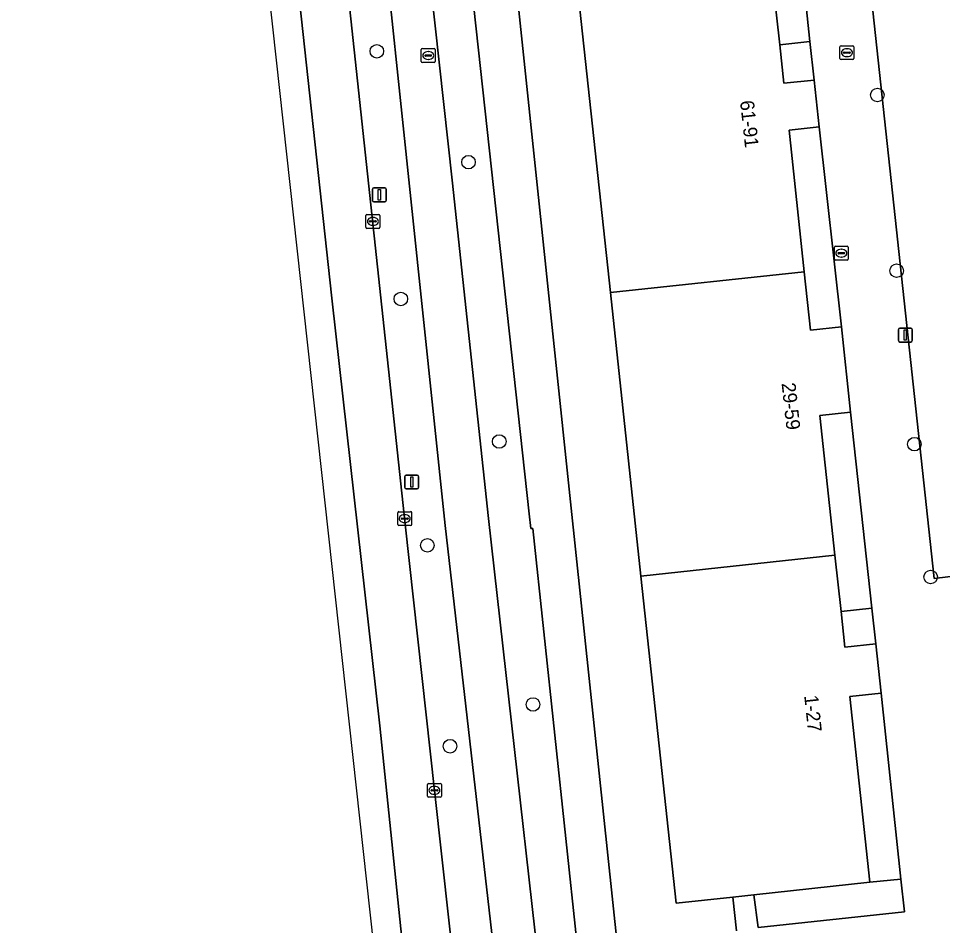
# Model space of a CAD drawing. Extents: x 161248 to 161848, y 384871 to 385383.
# Drawn here: x 161255.9 to 161322.5, y 385046.9 to 385112.2 of the extents above; entities that cross this region are included whole.
import ezdxf

# ---------------------------------------------------------------- set-up
doc = ezdxf.new("R2010")
doc.units = 0
for name, color, linetype in [('IMGEO_Berm_groen', 7, 'Continuous'), ('IMGEO_Boom', 7, 'Continuous'), ('IMGEO_Brandkraan', 7, 'Continuous'), ('IMGEO_Fietspad_gesloten', 7, 'Continuous'), ('IMGEO_Groenvoorziening', 7, 'Continuous'), ('IMGEO_Kolk', 7, 'Continuous'), ('IMGEO_Lichtmast', 7, 'Continuous'), ('IMGEO_OVBaan_gesloten', 7, 'Continuous'), ('IMGEO_Pand', 7, 'Continuous'), ('IMGEO_Pand_nummerreeks', 7, 'Continuous'), ('IMGEO_Parkeervlak_open', 7, 'Continuous'), ('IMGEO_Rioolput', 7, 'Continuous'), ('IMGEO_Voetpad_open', 7, 'Continuous')]:
    doc.layers.add(name, color=color, linetype=linetype)

msp = doc.modelspace()

# ---------------------------------------------------------------- linework, layer by layer
at = {"layer": 'IMGEO_Berm_groen'}
for points in [[(161256.654, 385321.916), (161257.172, 385317.445), (161257.661, 385313.23), (161259.702, 385295.859), (161261.967, 385276.513), (161264.604, 385254.141), (161265.807, 385244.078), (161266.037, 385241.979), (161266.267, 385239.966), (161268.56, 385218.577), (161268.655, 385216.841), (161268.939, 385214.138), (161270.794, 385196.453), (161276.441, 385144.086), (161283.784, 385075.774), (161285.879, 385056.617), (161288.02, 385037.301), (161290.772, 385012.005), (161294.901, 384976.402), (161297.066, 384956.529), (161299.154, 384937.372), (161301.048, 384920.049), (161301.427, 384916.232), (161301.431, 384916.18)], [(161275.66, 385206.665), (161282.325, 385144.732), (161283.468, 385134.103), (161287.158, 385100.538), (161289.778, 385076.19), (161294.971, 385029.929), (161297.713, 385030.826), (161292.978, 385075.471), (161292.829, 385075.469), (161292.7, 385076.509), (161285.204, 385145.048)], [(161304.405, 384916.554), (161304.284, 384917.771), (161304.157, 384919.005), (161298.845, 384967.161), (161292.634, 385023.456), (161286.649, 385075.675), (161279.435, 385144.415)]]:
    msp.add_lwpolyline(points, dxfattribs=at)
at = {"layer": 'IMGEO_Boom'}
for centre in [(161281.733, 385109.811), (161317.773, 385106.667), (161288.335, 385101.832), (161319.163, 385094.019), (161283.464, 385091.987), (161290.547, 385081.724), (161320.439, 385081.536), (161285.374, 385074.251), (161321.612, 385071.974), (161292.98, 385062.798), (161287.005, 385059.792)]:
    msp.add_circle(centre, 0.489, dxfattribs=at)
at = {"layer": 'IMGEO_Brandkraan'}
for p, q in [((161315.083, 385109.287), (161315.083, 385110.139)), ((161315.158, 385110.213), (161316.01, 385110.213)), ((161315.342, 385109.707), (161315.342, 385109.719)), ((161315.385, 385109.756), (161315.783, 385109.756)), ((161315.571, 385109.993), (161315.596, 385109.993)), ((161315.826, 385109.719), (161315.826, 385109.707)), ((161316.084, 385110.139), (161316.084, 385109.287)), ((161316.01, 385109.213), (161315.158, 385109.213)), ((161315.78, 385109.67), (161315.382, 385109.67)), ((161315.594, 385109.433), (161315.569, 385109.433))]:
    msp.add_line(p, q, dxfattribs=at)
for points in [[(161315.083, 385109.287), (161315.083, 385110.139)], [(161315.158, 385110.213), (161316.01, 385110.213)], [(161316.084, 385110.139), (161316.084, 385109.287)], [(161316.01, 385109.213), (161315.158, 385109.213)]]:
    msp.add_lwpolyline(points, dxfattribs=at)
for centre, radius, start, end in [((161315.16, 385110.137), 0.0765, 91.55205, 178.44795), ((161315.16, 385110.137), 0.0765, 91.55205, 178.44795), ((161315.382, 385109.716), 0.0403, 85.87752, 175.75265), ((161315.379, 385109.706), 0.0366, 178.93798, 274.71019), ((161315.783, 385109.713), 0.043, 264.86636, 352.45326), ((161315.787, 385109.718), 0.0386, 1.73085, 96.63898), ((161316.008, 385110.137), 0.0765, 1.55205, 88.44795), ((161316.008, 385110.137), 0.0765, 1.55205, 88.44795), ((161315.16, 385109.289), 0.0765, 181.55205, 268.44795), ((161315.16, 385109.289), 0.0765, 181.55205, 268.44795), ((161316.008, 385109.289), 0.0765, 271.55205, 358.44795), ((161316.008, 385109.289), 0.0765, 271.55205, 358.44795)]:
    msp.add_arc(centre, radius, start, end, dxfattribs=at)
for centre, major_axis, ratio, start_param, end_param in [((161315.57, 385109.713), (-0.387, 0.002), 0.722429, 4.712389, 7.853982), ((161315.595, 385109.713), (-0.39, 0.002), 0.717154, 1.570796, 4.712389)]:
    msp.add_ellipse(centre, major_axis=major_axis, ratio=ratio, start_param=start_param, end_param=end_param, dxfattribs=at)
at = {"layer": 'IMGEO_Fietspad_gesloten'}
for points in [[(161255.931, 385327.627), (161256.339, 385324.574), (161264.625, 385325.002), (161264.745, 385322.761), (161265.427, 385312.935), (161265.987, 385305.638), (161266.061, 385304.636), (161266.954, 385291.9), (161268.918, 385265.585), (161269.728, 385255.799), (161270.412, 385243.981), (161271.091, 385227.08), (161272.519, 385207.639), (161273.278, 385201.438), (161279.435, 385144.415), (161286.649, 385075.675), (161292.634, 385023.456), (161298.845, 384967.161), (161304.157, 384919.005), (161304.284, 384917.771), (161304.405, 384916.554)], [(161295.082, 385029.016), (161294.971, 385029.929), (161289.778, 385076.19), (161287.158, 385100.538), (161283.468, 385134.103), (161282.325, 385144.732), (161275.66, 385206.665)]]:
    msp.add_lwpolyline(points, dxfattribs=at)
at = {"layer": 'IMGEO_Groenvoorziening'}
for points in [[(161288.519, 385145.411), (161295.732, 385076.938), (161299.044, 385045.595)], [(161307.622, 385046.516), (161307.357, 385048.936), (161303.279, 385048.497), (161300.745, 385072.04), (161298.549, 385092.443), (161296.352, 385112.845)]]:
    msp.add_lwpolyline(points, dxfattribs=at)
at = {"layer": 'IMGEO_Kolk'}
for p, q in [((161280.95, 385097.143), (161280.95, 385097.995)), ((161281.025, 385098.069), (161281.877, 385098.069)), ((161281.438, 385097.849), (161281.463, 385097.849)), ((161281.951, 385097.995), (161281.951, 385097.143)), ((161281.877, 385097.069), (161281.025, 385097.069)), ((161281.209, 385097.563), (161281.209, 385097.575)), ((161281.647, 385097.526), (161281.249, 385097.526)), ((161281.252, 385097.612), (161281.65, 385097.612)), ((161281.461, 385097.289), (161281.436, 385097.289)), ((161281.693, 385097.575), (161281.693, 385097.563)), ((161283.241, 385075.749), (161283.241, 385076.601)), ((161283.316, 385076.675), (161284.168, 385076.675)), ((161283.729, 385076.455), (161283.754, 385076.455)), ((161284.242, 385076.601), (161284.242, 385075.749)), ((161283.5, 385076.169), (161283.5, 385076.181)), ((161283.938, 385076.132), (161283.54, 385076.132)), ((161283.543, 385076.218), (161283.941, 385076.218)), ((161283.752, 385075.895), (161283.727, 385075.895)), ((161283.984, 385076.181), (161283.984, 385076.169)), ((161284.168, 385075.675), (161283.316, 385075.675)), ((161285.453, 385057.117), (161286.305, 385057.117)), ((161285.378, 385056.191), (161285.378, 385057.043)), ((161285.637, 385056.611), (161285.637, 385056.623)), ((161286.075, 385056.574), (161285.677, 385056.574)), ((161285.68, 385056.66), (161286.078, 385056.66)), ((161285.866, 385056.897), (161285.891, 385056.897)), ((161286.121, 385056.623), (161286.121, 385056.611)), ((161286.379, 385057.043), (161286.379, 385056.191)), ((161286.305, 385056.117), (161285.453, 385056.117)), ((161285.889, 385056.337), (161285.864, 385056.337))]:
    msp.add_line(p, q, dxfattribs=at)
for points in [[(161280.95, 385097.143), (161280.95, 385097.995)], [(161281.025, 385098.069), (161281.877, 385098.069)], [(161281.951, 385097.995), (161281.951, 385097.143)], [(161281.877, 385097.069), (161281.025, 385097.069)], [(161283.241, 385075.749), (161283.241, 385076.601)], [(161283.316, 385076.675), (161284.168, 385076.675)], [(161284.242, 385076.601), (161284.242, 385075.749)], [(161284.168, 385075.675), (161283.316, 385075.675)], [(161285.453, 385057.117), (161286.305, 385057.117)], [(161285.378, 385056.191), (161285.378, 385057.043)], [(161286.379, 385057.043), (161286.379, 385056.191)], [(161286.305, 385056.117), (161285.453, 385056.117)]]:
    msp.add_lwpolyline(points, dxfattribs=at)
for centre, radius, start, end in [((161281.027, 385097.993), 0.0765, 91.55205, 178.44795), ((161281.027, 385097.993), 0.0765, 91.55205, 178.44795), ((161281.875, 385097.993), 0.0765, 1.55205, 88.44795), ((161281.875, 385097.993), 0.0765, 1.55205, 88.44795), ((161281.027, 385097.145), 0.0765, 181.55205, 268.44795), ((161281.027, 385097.145), 0.0765, 181.55205, 268.44795), ((161281.249, 385097.572), 0.0403, 85.87752, 175.75265), ((161281.246, 385097.562), 0.0366, 178.93798, 274.71019), ((161281.65, 385097.569), 0.043, 264.86636, 352.45326), ((161281.654, 385097.574), 0.0386, 1.73085, 96.63898), ((161281.875, 385097.145), 0.0765, 271.55205, 358.44795), ((161281.875, 385097.145), 0.0765, 271.55205, 358.44795), ((161283.318, 385076.599), 0.0765, 91.55205, 178.44795), ((161283.318, 385076.599), 0.0765, 91.55205, 178.44795), ((161284.166, 385076.599), 0.0765, 1.55205, 88.44795), ((161284.166, 385076.599), 0.0765, 1.55205, 88.44795), ((161283.318, 385075.751), 0.0765, 181.55205, 268.44795), ((161283.318, 385075.751), 0.0765, 181.55205, 268.44795), ((161283.54, 385076.178), 0.0403, 85.87752, 175.75265), ((161283.537, 385076.168), 0.0366, 178.93798, 274.71019), ((161283.941, 385076.175), 0.043, 264.86636, 352.45326), ((161283.945, 385076.18), 0.0386, 1.73085, 96.63898), ((161284.166, 385075.751), 0.0765, 271.55205, 358.44795), ((161284.166, 385075.751), 0.0765, 271.55205, 358.44795), ((161285.455, 385057.041), 0.0765, 91.55205, 178.44795), ((161285.455, 385057.041), 0.0765, 91.55205, 178.44795), ((161286.303, 385057.041), 0.0765, 1.55205, 88.44795), ((161286.303, 385057.041), 0.0765, 1.55205, 88.44795), ((161285.677, 385056.62), 0.0403, 85.87752, 175.75265), ((161285.674, 385056.61), 0.0366, 178.93798, 274.71019), ((161286.078, 385056.617), 0.043, 264.86636, 352.45326), ((161286.082, 385056.622), 0.0386, 1.73085, 96.63898), ((161285.455, 385056.193), 0.0765, 181.55205, 268.44795), ((161285.455, 385056.193), 0.0765, 181.55205, 268.44795), ((161286.303, 385056.193), 0.0765, 271.55205, 358.44795), ((161286.303, 385056.193), 0.0765, 271.55205, 358.44795)]:
    msp.add_arc(centre, radius, start, end, dxfattribs=at)
for centre, major_axis, ratio, start_param, end_param in [((161281.437, 385097.569), (-0.387, 0.002), 0.722429, 4.712389, 7.853982), ((161281.462, 385097.569), (-0.39, 0.002), 0.717154, 1.570796, 4.712389), ((161283.728, 385076.175), (-0.387, 0.002), 0.722429, 4.712389, 7.853982), ((161283.753, 385076.175), (-0.39, 0.002), 0.717154, 1.570796, 4.712389), ((161285.865, 385056.617), (-0.387, 0.002), 0.722429, 4.712389, 7.853982), ((161285.89, 385056.617), (-0.39, 0.002), 0.717154, 1.570796, 4.712389)]:
    msp.add_ellipse(centre, major_axis=major_axis, ratio=ratio, start_param=start_param, end_param=end_param, dxfattribs=at)
at = {"layer": 'IMGEO_Lichtmast'}
for p, q in [((161281.419, 385099.082), (161281.419, 385099.882)), ((161281.419, 385099.882), (161281.419, 385099.082)), ((161281.519, 385099.982), (161282.309, 385099.982)), ((161282.309, 385099.982), (161281.519, 385099.982)), ((161282.409, 385099.882), (161282.409, 385099.082)), ((161282.409, 385099.082), (161282.409, 385099.882)), ((161282.309, 385098.982), (161281.519, 385098.982)), ((161281.519, 385098.982), (161282.309, 385098.982)), ((161319.289, 385088.984), (161319.289, 385089.784)), ((161319.289, 385089.784), (161319.289, 385088.984)), ((161319.389, 385089.884), (161320.179, 385089.884)), ((161320.179, 385089.884), (161319.389, 385089.884)), ((161320.279, 385089.784), (161320.279, 385088.984)), ((161320.279, 385088.984), (161320.279, 385089.784)), ((161320.179, 385088.884), (161319.389, 385088.884)), ((161319.389, 385088.884), (161320.179, 385088.884)), ((161283.756, 385078.409), (161283.756, 385079.209)), ((161283.756, 385079.209), (161283.756, 385078.409)), ((161283.856, 385079.309), (161284.646, 385079.309)), ((161284.646, 385079.309), (161283.856, 385079.309)), ((161284.746, 385079.209), (161284.746, 385078.409)), ((161284.746, 385078.409), (161284.746, 385079.209)), ((161284.646, 385078.309), (161283.856, 385078.309)), ((161283.856, 385078.309), (161284.646, 385078.309))]:
    msp.add_line(p, q, dxfattribs=at)
for points in [[(161281.839, 385099.857), (161281.989, 385099.857), (161281.989, 385099.107), (161281.839, 385099.107), (161281.839, 385099.857)], [(161319.709, 385089.759), (161319.859, 385089.759), (161319.859, 385089.009), (161319.709, 385089.009), (161319.709, 385089.759)], [(161284.176, 385079.184), (161284.326, 385079.184), (161284.326, 385078.434), (161284.176, 385078.434), (161284.176, 385079.184)]]:
    msp.add_lwpolyline(points, dxfattribs=at)
for centre, start, end in [((161281.519, 385099.882), 90, 180), ((161281.519, 385099.882), 90, 180), ((161282.309, 385099.882), 0, 90), ((161282.309, 385099.882), 360, 90), ((161281.519, 385099.082), 180, 270), ((161281.519, 385099.082), 180, 270), ((161282.309, 385099.082), 270, 0), ((161282.309, 385099.082), 270, 0), ((161319.389, 385089.784), 90, 180), ((161319.389, 385089.784), 90, 180), ((161320.179, 385089.784), 0, 90), ((161320.179, 385089.784), 360, 90), ((161319.389, 385088.984), 180, 270), ((161319.389, 385088.984), 180, 270), ((161320.179, 385088.984), 270, 0), ((161320.179, 385088.984), 270, 0), ((161283.856, 385079.209), 90, 180), ((161283.856, 385079.209), 90, 180), ((161284.646, 385079.209), 0, 90), ((161284.646, 385079.209), 360, 90), ((161283.856, 385078.409), 180, 270), ((161283.856, 385078.409), 180, 270), ((161284.646, 385078.409), 270, 0), ((161284.646, 385078.409), 270, 0)]:
    msp.add_arc(centre, 0.1, start, end, dxfattribs=at)
at = {"layer": 'IMGEO_OVBaan_gesloten'}
msp.add_lwpolyline([(161295.965, 384918.881), (161297.553, 384919.307), (161294.791, 384944.716), (161294.575, 384946.289), (161289.927, 384984.269), (161281.959, 385061.27), (161278.495, 385092.054), (161272.888, 385143.697), (161270.729, 385143.46), (161284.246, 385020.36), (161293.774, 384933.589), (161295.965, 384918.881)], dxfattribs=at)
msp.add_lwpolyline([(161283.784, 385075.774), (161276.441, 385144.086), (161272.888, 385143.697), (161278.495, 385092.054), (161281.959, 385061.27), (161289.927, 384984.269), (161294.575, 384946.289), (161294.791, 384944.716), (161297.553, 384919.307), (161301.048, 384920.049), (161299.154, 384937.372), (161297.066, 384956.529), (161294.901, 384976.402), (161290.772, 385012.005), (161288.02, 385037.301), (161285.879, 385056.617)], close=True, dxfattribs=at)
at = {"layer": 'IMGEO_Pand'}
for points in [[(161311.415, 385104.141), (161313.581, 385104.374), (161313.218, 385107.745), (161311.042, 385107.511), (161310.744, 385110.276), (161310.306, 385114.346), (161296.352, 385112.845), (161298.549, 385092.443), (161312.512, 385093.945)], [(161313.639, 385083.604), (161315.846, 385083.841), (161315.186, 385089.98), (161312.965, 385089.741), (161312.512, 385093.945), (161298.549, 385092.443), (161300.745, 385072.04), (161314.722, 385073.544)], [(161315.797, 385063.373), (161318.042, 385063.615), (161317.659, 385067.169), (161315.435, 385066.929), (161315.158, 385069.497), (161314.722, 385073.544), (161300.745, 385072.04), (161303.279, 385048.497), (161307.357, 385048.936), (161308.872, 385049.099), (161317.236, 385050)]]:
    msp.add_lwpolyline(points, close=True, dxfattribs=at)
at = {"layer": 'IMGEO_Parkeervlak_open'}
msp.add_lwpolyline([(161313.501, 385149.174), (161321.861, 385071.864), (161326.412, 385072.422)], dxfattribs=at)
at = {"layer": 'IMGEO_Rioolput'}
for p, q in [((161284.936, 385109.084), (161284.936, 385109.936)), ((161285.011, 385110.01), (161285.863, 385110.01)), ((161285.424, 385109.79), (161285.449, 385109.79)), ((161285.937, 385109.936), (161285.937, 385109.084)), ((161285.863, 385109.01), (161285.011, 385109.01)), ((161285.195, 385109.504), (161285.195, 385109.516)), ((161285.633, 385109.467), (161285.235, 385109.467)), ((161285.238, 385109.553), (161285.636, 385109.553)), ((161285.447, 385109.23), (161285.422, 385109.23)), ((161285.679, 385109.516), (161285.679, 385109.504)), ((161314.679, 385094.854), (161314.679, 385095.706)), ((161314.754, 385095.78), (161315.606, 385095.78)), ((161315.68, 385095.706), (161315.68, 385094.854)), ((161314.938, 385095.274), (161314.938, 385095.286)), ((161315.376, 385095.237), (161314.978, 385095.237)), ((161314.981, 385095.323), (161315.379, 385095.323)), ((161315.167, 385095.56), (161315.192, 385095.56)), ((161315.422, 385095.286), (161315.422, 385095.274)), ((161315.606, 385094.78), (161314.754, 385094.78)), ((161315.19, 385095), (161315.165, 385095))]:
    msp.add_line(p, q, dxfattribs=at)
for points in [[(161284.936, 385109.084), (161284.936, 385109.936)], [(161285.011, 385110.01), (161285.863, 385110.01)], [(161285.937, 385109.936), (161285.937, 385109.084)], [(161285.863, 385109.01), (161285.011, 385109.01)], [(161314.679, 385094.854), (161314.679, 385095.706)], [(161314.754, 385095.78), (161315.606, 385095.78)], [(161315.68, 385095.706), (161315.68, 385094.854)], [(161315.606, 385094.78), (161314.754, 385094.78)]]:
    msp.add_lwpolyline(points, dxfattribs=at)
for centre, radius, start, end in [((161285.013, 385109.934), 0.0765, 91.55205, 178.44795), ((161285.013, 385109.934), 0.0765, 91.55205, 178.44795), ((161285.861, 385109.934), 0.0765, 1.55205, 88.44795), ((161285.861, 385109.934), 0.0765, 1.55205, 88.44795), ((161285.013, 385109.086), 0.0765, 181.55205, 268.44795), ((161285.013, 385109.086), 0.0765, 181.55205, 268.44795), ((161285.235, 385109.513), 0.0403, 85.87752, 175.75265), ((161285.232, 385109.503), 0.0366, 178.93798, 274.71019), ((161285.636, 385109.51), 0.043, 264.86636, 352.45326), ((161285.64, 385109.515), 0.0386, 1.73085, 96.63898), ((161285.861, 385109.086), 0.0765, 271.55205, 358.44795), ((161285.861, 385109.086), 0.0765, 271.55205, 358.44795), ((161314.756, 385095.704), 0.0765, 91.55205, 178.44795), ((161314.756, 385095.704), 0.0765, 91.55205, 178.44795), ((161315.604, 385095.704), 0.0765, 1.55205, 88.44795), ((161315.604, 385095.704), 0.0765, 1.55205, 88.44795), ((161314.978, 385095.283), 0.0403, 85.87752, 175.75265), ((161314.975, 385095.273), 0.0366, 178.93798, 274.71019), ((161315.379, 385095.28), 0.043, 264.86636, 352.45326), ((161315.383, 385095.285), 0.0386, 1.73085, 96.63898), ((161314.756, 385094.856), 0.0765, 181.55205, 268.44795), ((161314.756, 385094.856), 0.0765, 181.55205, 268.44795), ((161315.604, 385094.856), 0.0765, 271.55205, 358.44795), ((161315.604, 385094.856), 0.0765, 271.55205, 358.44795)]:
    msp.add_arc(centre, radius, start, end, dxfattribs=at)
for centre, major_axis, ratio, start_param, end_param in [((161285.423, 385109.51), (-0.387, 0.002), 0.722429, 4.712389, 7.853982), ((161285.448, 385109.51), (-0.39, 0.002), 0.717154, 1.570796, 4.712389), ((161315.166, 385095.28), (-0.387, 0.002), 0.722429, 4.712389, 7.853982), ((161315.191, 385095.28), (-0.39, 0.002), 0.717154, 1.570796, 4.712389)]:
    msp.add_ellipse(centre, major_axis=major_axis, ratio=ratio, start_param=start_param, end_param=end_param, dxfattribs=at)
at = {"layer": 'IMGEO_Voetpad_open'}
for points in [[(161275.697, 385233.018), (161279.427, 385198.062), (161285.204, 385145.048), (161292.7, 385076.509), (161292.829, 385075.469), (161292.978, 385075.471), (161297.713, 385030.826)], [(161299.044, 385045.595), (161295.732, 385076.938), (161288.519, 385145.411), (161287.873, 385151.4), (161287.866, 385151.482), (161287.864, 385151.639), (161287.875, 385151.796), (161287.901, 385151.951), (161287.94, 385152.103), (161287.993, 385152.251), (161288.058, 385152.393), (161288.137, 385152.53), (161288.227, 385152.658), (161288.328, 385152.779), (161288.439, 385152.889), (161288.56, 385152.989), (161288.69, 385153.078), (161288.827, 385153.156), (161288.97, 385153.22), (161289.118, 385153.272), (161289.271, 385153.31), (161289.426, 385153.334), (161289.281, 385155.459)], [(161326.412, 385072.422), (161321.861, 385071.864), (161313.501, 385149.174)], [(161311.424, 385124.852), (161312.921, 385110.511), (161313.218, 385107.745), (161313.581, 385104.374), (161315.186, 385089.98), (161315.846, 385083.841), (161317.383, 385069.737), (161317.659, 385067.169), (161318.042, 385063.615), (161319.468, 385050.224), (161319.721, 385047.865), (161309.184, 385046.74), (161308.872, 385049.099), (161307.357, 385048.936), (161307.622, 385046.516)]]:
    msp.add_lwpolyline(points, dxfattribs=at)
for points in [[(161311.424, 385124.852), (161309.2, 385124.612), (161310.306, 385114.346), (161310.744, 385110.276), (161312.921, 385110.511)], [(161312.921, 385110.511), (161310.744, 385110.276), (161311.042, 385107.511), (161313.218, 385107.745)], [(161313.581, 385104.374), (161311.415, 385104.141), (161312.512, 385093.945), (161312.965, 385089.741), (161315.186, 385089.98)], [(161315.846, 385083.841), (161313.639, 385083.604), (161314.722, 385073.544), (161315.158, 385069.497), (161317.383, 385069.737)], [(161317.383, 385069.737), (161315.158, 385069.497), (161315.435, 385066.929), (161317.659, 385067.169)], [(161318.042, 385063.615), (161315.797, 385063.373), (161317.236, 385050), (161319.468, 385050.224)], [(161319.468, 385050.224), (161317.236, 385050), (161308.872, 385049.099), (161309.184, 385046.74), (161319.721, 385047.865)]]:
    msp.add_lwpolyline(points, close=True, dxfattribs=at)

# ---------------------------------------------------------------- texts
at = {"layer": 'IMGEO_Pand_nummerreeks'}
for s, rotation, p in [('61-91', 276.17627, (161307.884, 385106.231)), ('29-59', 276.1419, (161310.876, 385085.914)), ('1-27', 276.09606, (161312.504, 385063.424))]:
    msp.add_text(s, height=1, rotation=rotation, dxfattribs=at).set_placement(p)

doc.saveas('drawing.dxf')
